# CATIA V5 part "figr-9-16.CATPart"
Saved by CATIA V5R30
Part number: Part1
Bounding box of the stored display mesh (mm): x -77.304 to 77.304, y -77.304 to 125.507, z 0 to 125
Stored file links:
  D:\PROJECTS\CATIA V56R 2020\Resources\Parts File\c09_catia_v5_6r2020_prt\figr-9-16.CATPart
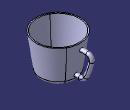
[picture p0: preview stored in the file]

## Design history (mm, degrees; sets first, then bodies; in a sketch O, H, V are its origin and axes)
Set1
  Plane1: type Normal, Curve Sketch3, RefPoint vertex of Sketch3
Body1 (main body)
  Sketch1 on yz-plane, origin (0, 0, 0), H (0, 1, 0), V (0, 0, 1)
    line L1 (0, 0) -> (60, 0)
    point P1 (60, 0)
    point P2 (60, 0)
    line L2 (60, 0) -> (77.5, 125)
    point P3 (77.5, 125)
    line L3 (77.5, 125) -> (0, 125)
    point P4 (0, 125)
    line L4 (0, 125) -> (0, 0)
    axis line L5 (0, 150.2858) -> (0, -31.0593)
    point P5 (0, 150.2858)
    radius about axis P1 L5 = 60
    radius about axis P3 L5 = 77.5
    distance L3 L1 = 125
    horizontal: L1 H, L3 H
    coincidence: P4 V, P2 P1, P5 V
    vertical: L4 V, L5 V
  Shaft1: profile Sketch1, axis Sketch1.L5, angle 360
  Fillet1: radius 15, on edge [face of Shaft1 | face of Shaft1]
  Shell1: ExtOffset 0, Face face of Shaft1, IntOffset 4
  Sketch2 on Plane1, origin (0, 62.9841, 0), H (-1, 0, 0), V (0, 0, 1)
    circle A1 centre (0, 22.002) radius 7.5
    reference projected point E1 (0, 22.002) from vertex of Sketch3
    radius A1 = 7.5
    concentricity: A1 E1
  Sketch3 on yz-plane, origin (0, 0, 0), H (0, 1, 0), V (0, 0, 1)
    line L1 (62.9841, 22.002) -> (78.2172, 22.002)
    arc A1 centre (78.2172, 44.1133) radius 22.1113 from (78.2172, 22.002) to (97.9307, 34.0988) ccw
    arc A2 centre (-112.3295, 140.9107) radius 235.8349 from (97.9307, 34.0988) to (117.8681, 89.6549) ccw
    arc A3 centre (104.0328, 92.7355) radius 14.1742 from (117.8681, 89.6549) to (104.4272, 106.9041) ccw
    arc A4 centre (93.6744, -279.4123) radius 386.4661 from (104.4272, 106.9041) to (82.9216, 106.9041) ccw
    horizontal: L1 H
    tangency: A1 L1, A2 A1, A3 A2, A4 A3
  Rib1: profile Sketch2, centre curve Sketch3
